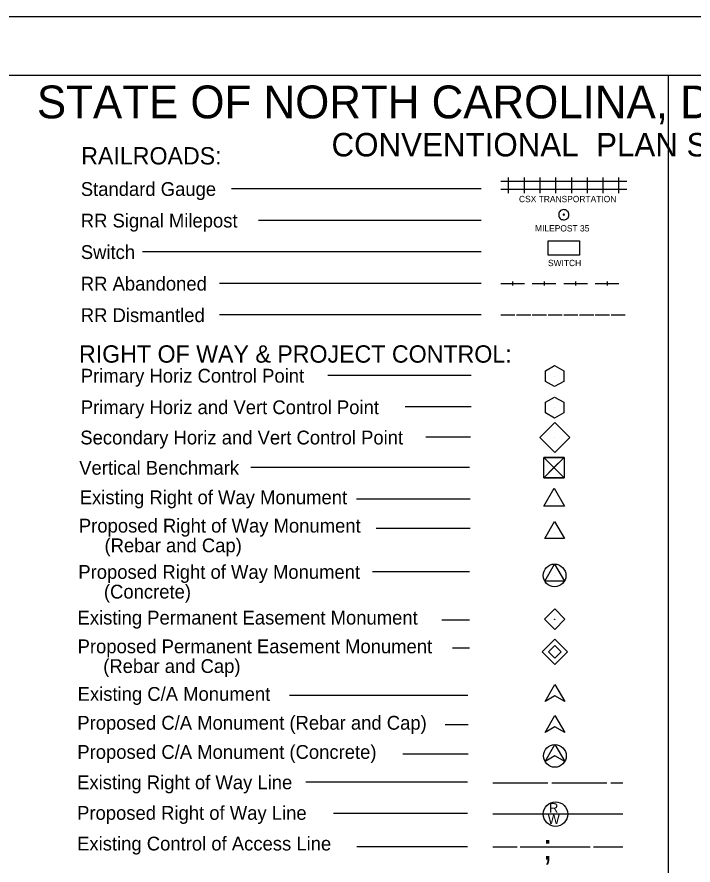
# Model space of a CAD drawing. Extents: x 2040834 to 2047174, y 618431 to 621625.
# Drawn here: x 2045579 to 2046085, y 620991 to 621625 of the extents above; entities that cross this region are included whole.
import ezdxf

# ---------------------------------------------------------------- set-up
doc = ezdxf.new("R2010")
doc.units = 0
doc.layers.add('Default', color=7, linetype='Continuous')

msp = doc.modelspace()

# ---------------------------------------------------------------- linework, layer by layer
at = {"layer": 'Default'}
for p, q in [((2047057.71, 621624.54), (2045074.38, 621624.54)), ((2047013.96, 621580.79), (2045118.13, 621580.79)), ((2046066.04, 621580.79), (2046066.01, 620384.96)), ((2045940.95, 621501.82), (2045952.72, 621501.82)), ((2045946.84, 621492.99), (2045946.84, 621504.76)), ((2045952.72, 621501.82), (2045964.49, 621501.82)), ((2045958.61, 621492.99), (2045958.61, 621504.76)), ((2045964.49, 621501.82), (2045976.26, 621501.82)), ((2045970.38, 621492.99), (2045970.38, 621504.76)), ((2045976.26, 621501.82), (2045988.04, 621501.82)), ((2045982.15, 621492.99), (2045982.15, 621504.76)), ((2045988.04, 621501.82), (2045999.81, 621501.82)), ((2045993.92, 621492.99), (2045993.92, 621504.76)), ((2045999.81, 621501.82), (2046011.58, 621501.82)), ((2046005.69, 621492.99), (2046005.69, 621504.76)), ((2046011.58, 621501.82), (2046023.35, 621501.82)), ((2046017.46, 621492.99), (2046017.46, 621504.76)), ((2046023.35, 621501.82), (2046035.12, 621501.82)), ((2046029.23, 621492.99), (2046029.23, 621504.76)), ((2045926.36, 621496.21), (2045739.9, 621496.21)), ((2045940.95, 621495.93), (2045952.72, 621495.93)), ((2045952.72, 621495.93), (2045964.49, 621495.93)), ((2045964.49, 621495.93), (2045976.26, 621495.93)), ((2045976.26, 621495.93), (2045988.04, 621495.93)), ((2045988.04, 621495.93), (2045999.81, 621495.93)), ((2045999.81, 621495.93), (2046011.58, 621495.93)), ((2046011.58, 621495.93), (2046023.35, 621495.93)), ((2046023.35, 621495.93), (2046035.12, 621495.93)), ((2045926.36, 621472.67), (2045760.07, 621472.67)), ((2045926.36, 621449.13), (2045673.39, 621449.13)), ((2045926.36, 621425.59), (2045730.78, 621425.59)), ((2045940.95, 621425.59), (2045958.61, 621425.59)), ((2045949.78, 621427.06), (2045949.78, 621424.11)), ((2045964.49, 621425.59), (2045982.15, 621425.59)), ((2045973.32, 621427.06), (2045973.32, 621424.11)), ((2045988.04, 621425.59), (2046005.69, 621425.59)), ((2045996.86, 621427.06), (2045996.86, 621424.11)), ((2046011.58, 621425.59), (2046029.23, 621425.59)), ((2046020.41, 621427.06), (2046020.41, 621424.11)), ((2045926.36, 621402.04), (2045730.78, 621402.04)), ((2045926.36, 621402.04), (2045730.78, 621402.04)), ((2045940.95, 621402.04), (2045951.55, 621402.04)), ((2045952.72, 621402.04), (2045963.32, 621402.04)), ((2045964.49, 621402.04), (2045975.09, 621402.04)), ((2045976.26, 621402.04), (2045986.86, 621402.04)), ((2045988.04, 621402.04), (2045998.63, 621402.04)), ((2045999.81, 621402.04), (2046010.4, 621402.04)), ((2046011.58, 621402.04), (2046022.17, 621402.04)), ((2046023.35, 621402.04), (2046033.94, 621402.04)), ((2045918.82, 621356.85), (2045811.67, 621356.85)), ((2045981.13, 621356.42), (2045981.13, 621356.42)), ((2045918.82, 621333.31), (2045869.48, 621333.31)), ((2045981.11, 621332.91), (2045981.11, 621332.91)), ((2045918.45, 621310.7), (2045884.84, 621310.7)), ((2045981.28, 621310.46), (2045981.28, 621310.46)), ((2045917.64, 621288.08), (2045754.21, 621288.08)), ((2045980.69, 621288.1), (2045980.69, 621288.1)), ((2045918.01, 621264.56), (2045833.2, 621264.56)), ((2045918.13, 621242.45), (2045847.82, 621242.45)), ((2045981.12, 621239.37), (2045981.12, 621239.37)), ((2045917.53, 621210.19), (2045845.16, 621210.19)), ((2045981.14, 621207.52), (2045981.14, 621207.52)), ((2045917.63, 621174.06), (2045896.97, 621174.06)), ((2045981.23, 621174.83), (2045981.23, 621174.83)), ((2045917.63, 621153.32), (2045904.91, 621153.32)), ((2045981.44, 621150.58), (2045981.44, 621150.58)), ((2045974.06, 621113.41), (2045981.42, 621126.12)), ((2045981.42, 621126.12), (2045988.78, 621113.41)), ((2045916.46, 621117.75), (2045783.17, 621117.75)), ((2045981.42, 621117.65), (2045974.06, 621113.41)), ((2045988.78, 621113.41), (2045981.42, 621117.65)), ((2045974.03, 621090.32), (2045981.38, 621103.04)), ((2045981.38, 621103.04), (2045988.74, 621090.32)), ((2045916.58, 621095.94), (2045899.43, 621095.94)), ((2045981.38, 621094.56), (2045974.03, 621090.32)), ((2045988.74, 621090.32), (2045981.38, 621094.56)), ((2045974.03, 621068.54), (2045981.38, 621081.25)), ((2045981.38, 621081.25), (2045988.74, 621068.54)), ((2045916.58, 621074.15), (2045867.85, 621074.15)), ((2045981.38, 621072.78), (2045974.03, 621068.54)), ((2045988.74, 621068.54), (2045981.38, 621072.78)), ((2045916.06, 621053.22), (2045795.39, 621053.22)), ((2045934.93, 621052.55), (2045976.13, 621052.55)), ((2045979.07, 621052.55), (2046020.27, 621052.55)), ((2046023.21, 621052.55), (2046032.04, 621052.55)), ((2045916.06, 621029.68), (2045815.95, 621029.68)), ((2045934.93, 621029.54), (2046032.04, 621029.54)), ((2045916.06, 621004.82), (2045833.38, 621004.82)), ((2045934.93, 621004.82), (2045953.13, 621004.82)), ((2045955.48, 621004.82), (2046007.76, 621004.82)), ((2046010.11, 621004.82), (2046032.04, 621004.82))]:
    msp.add_line(p, q, dxfattribs=at)
for points in [[(2045991.87, 621476.86), (2045991.8, 621477.62), (2045991.57, 621478.39), (2045991.18, 621479.08), (2045990.65, 621479.61), (2045990.04, 621480.07), (2045989.35, 621480.45), (2045988.66, 621480.61), (2045987.82, 621480.68), (2045987.06, 621480.53), (2045986.37, 621480.3), (2045985.68, 621479.92), (2045985.14, 621479.38), (2045984.69, 621478.7), (2045984.38, 621478.01), (2045984.23, 621477.24), (2045984.23, 621476.48), (2045984.38, 621475.71), (2045984.69, 621475.03), (2045985.14, 621474.34), (2045985.68, 621473.8), (2045986.37, 621473.42), (2045987.06, 621473.19), (2045987.82, 621473.04), (2045988.66, 621473.11), (2045989.35, 621473.27), (2045990.04, 621473.65), (2045990.65, 621474.11), (2045991.18, 621474.64), (2045991.57, 621475.33), (2045991.8, 621476.09), (2045991.87, 621476.86)], [(2045988.2, 621477.32), (2045987.97, 621477.32), (2045987.74, 621477.17), (2045987.59, 621476.94), (2045987.67, 621476.71), (2045987.82, 621476.48), (2045988.05, 621476.4), (2045988.28, 621476.48), (2045988.43, 621476.63), (2045988.51, 621476.94), (2045988.43, 621477.17), (2045988.2, 621477.32)], [(2045981.13, 621348.58), (2045974.3, 621352.46), (2045974.3, 621360.29), (2045981.13, 621364.25), (2045987.95, 621360.37), (2045987.95, 621352.46), (2045981.13, 621348.58)], [(2045988.31, 621295.71), (2045973.04, 621280.45), (2045980.67, 621288.08), (2045988.31, 621280.45), (2045973.04, 621295.71)], [(2045980.67, 621288.08), (2045988.31, 621295.71), (2045973.04, 621295.71), (2045980.67, 621288.08)], [(2045980.67, 621288.08), (2045973.04, 621280.45), (2045988.31, 621280.45), (2045980.67, 621288.08)], [(2045973.16, 621259.31), (2045980.81, 621272.59), (2045988.45, 621259.31), (2045973.16, 621259.31)]]:
    msp.add_lwpolyline(points, dxfattribs=at)
for points in [[(2045976.26, 621457.32), (2045999.81, 621457.32), (2045999.81, 621446.61), (2045976.26, 621446.61)], [(2045974.25, 621336.89), (2045981.15, 621340.74), (2045988.06, 621336.94), (2045987.95, 621329.03), (2045981.05, 621325.02), (2045974.25, 621328.87)], [(2045970.2, 621310.5), (2045981.33, 621321.63), (2045992.48, 621310.48), (2045981.35, 621299.35)], [(2045973.04, 621295.71), (2045988.31, 621295.71), (2045988.31, 621280.45), (2045973.04, 621280.45)], [(2045973.76, 621235.13), (2045981.12, 621247.85), (2045988.48, 621235.13)], [(2045973.78, 621203.28), (2045981.14, 621215.99), (2045988.5, 621203.28)], [(2045973.59, 621174.83), (2045981.23, 621182.48), (2045988.88, 621174.83), (2045981.23, 621167.19)], [(2045981.44, 621160.06), (2045990.92, 621150.58), (2045981.44, 621141.1), (2045971.96, 621150.58)], [(2045981.44, 621155.32), (2045986.18, 621150.58), (2045981.44, 621145.84), (2045976.7, 621150.58)]]:
    msp.add_lwpolyline(points, close=True, dxfattribs=at)
for centre, radius in [((2045981.14, 621207.51), 8.48), ((2045981.23, 621174.83), 0.149), ((2045981.38, 621072.78), 8.48), ((2045981.84, 621029.29), 9.13)]:
    msp.add_circle(centre, radius, dxfattribs=at)

# ---------------------------------------------------------------- texts
for s, height, p in [('STATE OF NORTH CAROLINA, DIVISION OF HIGHWAYS', 24.5, (2045594.41, 621548.84)), ('CONVENTIONAL  PLAN SHEET SYMBOLS', 17.5, (2045814.5, 621520.41)), ('RAILROADS:', 12.948, (2045627.51, 621514.4)), ('Standard Gauge', 10.2996, (2045627.19, 621490.89)), ('RR Signal Milepost', 10.2996, (2045627.19, 621467.34)), ('Switch', 10.3, (2045627.19, 621443.8)), ('RR Abandoned', 10.2996, (2045627.19, 621420.26)), ('RR Dismantled', 10.2996, (2045627.19, 621396.72)), ('RIGHT OF WAY & PROJECT CONTROL:', 12.9481, (2045625.86, 621366.41)), ('Primary Horiz Control Point', 10.2996, (2045627.2, 621351.5)), ('Primary Horiz and Vert Control Point', 10.2996, (2045627.2, 621327.95)), ('Secondary Horiz and Vert Control Point', 10.2996, (2045626.83, 621305.35)), ('Vertical Benchmark', 10.2996, (2045626.01, 621282.73)), ('Existing Right of Way Monument', 10.2996, (2045626.38, 621260.7)), ('Proposed Right of Way Monument', 10.2996, (2045625.77, 621239.54)), ('     (Rebar and Cap)', 10.2996, (2045625.77, 621224.83)), ('Proposed Right of Way Monument', 10.2996, (2045625.33, 621204.99)), ('     (Concrete)', 10.2996, (2045625.33, 621190.28)), ('Existing Permanent Easement Monument', 10.2996, (2045624.76, 621170.87)), ('Proposed Permanent Easement Monument', 10.2996, (2045624.81, 621149.41)), ('     (Rebar and Cap)', 10.2996, (2045624.81, 621134.69)), ('Existing C/A Monument', 10.2996, (2045624.83, 621113.89)), ('Proposed C/A Monument (Rebar and Cap)', 10.2996, (2045624.59, 621092.34)), ('Proposed C/A Monument (Concrete)', 10.2996, (2045624.59, 621070.56)), ('Existing Right of Way Line', 10.2996, (2045624.43, 621047.87)), ('Proposed Right of Way Line', 10.2996, (2045624.43, 621025.06)), ('R', 7.15, (2045977.05, 621030.37)), ('W', 7.15, (2045976.03, 621021.95)), ('Existing Control of Access Line', 10.2996, (2045624.43, 621002.15)), (';', 19.42, (2045972.35, 620995.18))]:
    msp.add_text(s, height=height, dxfattribs=at).set_placement(p)
for s, height, p in [('CSX TRANSPORTATION', 4.7083, (2045954.56, 621486.24)), ('MILEPOST 35', 4.7083, (2045966.55, 621464.37)), ('SWITCH', 4.708, (2045976.21, 621438.48))]:
    msp.add_text(s, height=height, rotation=360, dxfattribs=at).set_placement(p)

doc.saveas('drawing.dxf')
